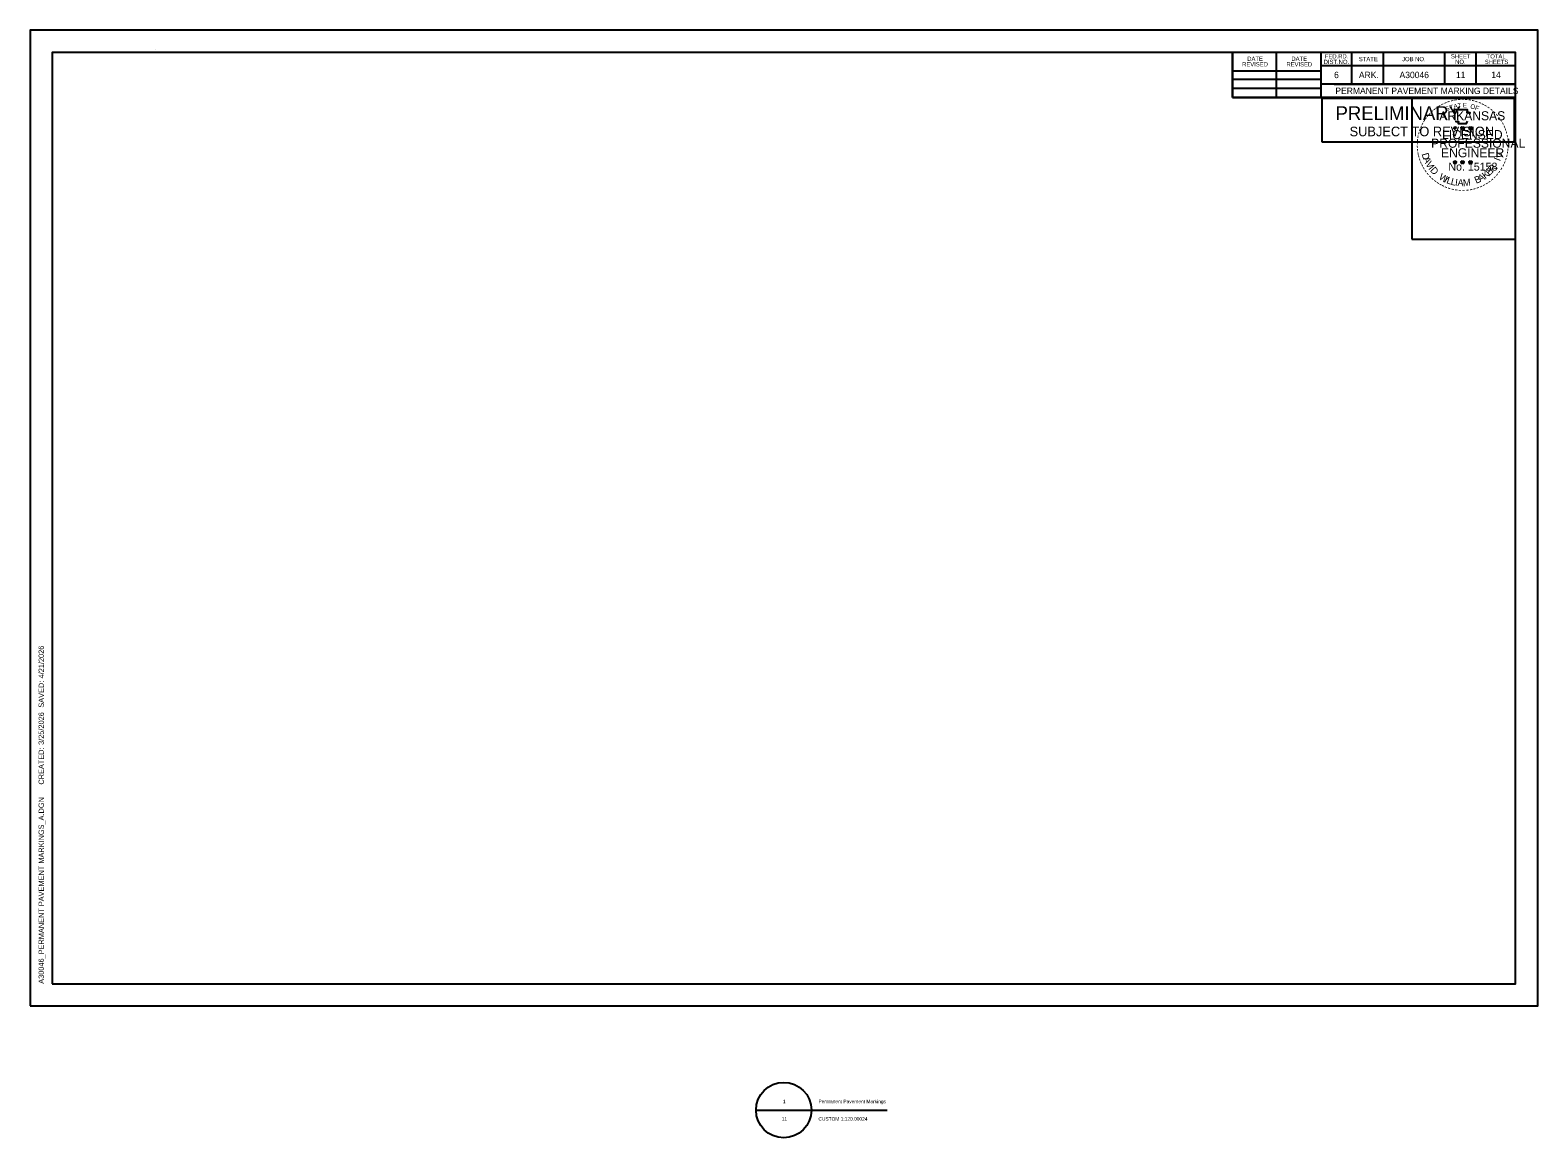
# Model space of a CAD drawing. Extents: x 0 to 1.42, y -0.12 to 0.92.
import ezdxf

# ---------------------------------------------------------------- set-up
doc = ezdxf.new("R2010")
doc.units = 0
for name, color, linetype in [('Default', 7, 'Continuous'), ('SHET_Annotations', 7, 'Continuous'), ('SHET_Border-Lines', 7, 'Continuous'), ('SHET_Border-Text', 7, 'Continuous'), ('SHET_Stamp-Prelim', 7, 'Continuous'), ('SHET_Stamp-Seal', 7, 'Continuous')]:
    doc.layers.add(name, color=color, linetype=linetype)

msp = doc.modelspace()

# ---------------------------------------------------------------- linework, layer by layer
at = {"layer": 'Default'}
for p, q in [((0.6821, -0.0979), (0.7341, -0.0979)), ((0.7083, -0.0979), (0.8052, -0.0979))]:
    msp.add_line(p, q, dxfattribs=at)
msp.add_circle((0.7081, -0.0979), 0.026, dxfattribs=at)
at = {"layer": 'SHET_Border-Lines'}
for p, q in [((0.1176, 0.8988), (0.1176, 0.8988)), ((0.1176, 0.8988), (0.1176, 0.8988)), ((1.1296, 0.8534), (1.1296, 0.8958)), ((1.1711, 0.8534), (1.1711, 0.8958)), ((1.2127, 0.8958), (1.2127, 0.8534)), ((1.2417, 0.8958), (1.2417, 0.866)), ((1.2712, 0.8958), (1.2712, 0.866)), ((1.3289, 0.8958), (1.3289, 0.866)), ((1.3584, 0.8958), (1.3584, 0.866)), ((1.1296, 0.8786), (1.2127, 0.8786)), ((1.3958, 0.8832), (1.2127, 0.8832)), ((1.3958, 0.8833), (1.3958, 0.8833)), ((1.1296, 0.8706), (1.2127, 0.8706)), ((1.3958, 0.866), (1.2127, 0.866)), ((1.2252, 0.866), (1.3958, 0.866)), ((1.1296, 0.8622), (1.2127, 0.8622)), ((1.3958, 0.8534), (1.1296, 0.8534))]:
    msp.add_line(p, q, dxfattribs=at)
for points in [[(0, 0), (1.4167, 0), (1.4167, 0.9167), (0, 0.9167)], [(0.0208, 0.0208), (1.3958, 0.0208), (1.3958, 0.8958), (0.0208, 0.8958)], [(1.1296, 0.8534), (1.3958, 0.8534), (1.3958, 0.8958), (1.1296, 0.8958)]]:
    msp.add_lwpolyline(points, close=True, dxfattribs=at)
at = {"layer": 'SHET_Stamp-Prelim'}
msp.add_lwpolyline([(1.2137, 0.8119), (1.3948, 0.8119), (1.3948, 0.8524), (1.2137, 0.8524)], close=True, dxfattribs=at)
at = {"layer": 'SHET_Stamp-Seal'}
for p, q in [((1.3373, 0.8252), (1.3388, 0.8247)), ((1.3373, 0.8252), (1.3384, 0.825)), ((1.3373, 0.8252), (1.3383, 0.8247)), ((1.3379, 0.8235), (1.3388, 0.8247)), ((1.3379, 0.8235), (1.3384, 0.8245)), ((1.3379, 0.8235), (1.3388, 0.8244)), ((1.3388, 0.8263), (1.3386, 0.8252)), ((1.3388, 0.8247), (1.3388, 0.8263)), ((1.3388, 0.8263), (1.339, 0.8252)), ((1.3403, 0.8252), (1.3388, 0.8247)), ((1.3397, 0.8235), (1.3388, 0.8247)), ((1.3397, 0.8235), (1.3388, 0.8244)), ((1.3403, 0.8252), (1.3391, 0.825)), ((1.3397, 0.8235), (1.3391, 0.8247)), ((1.3403, 0.8252), (1.3394, 0.8248)), ((1.3444, 0.8252), (1.3459, 0.8247)), ((1.3444, 0.8252), (1.3455, 0.825)), ((1.3444, 0.8252), (1.3454, 0.8247)), ((1.345, 0.8235), (1.3459, 0.8247)), ((1.345, 0.8235), (1.3455, 0.8245)), ((1.345, 0.8235), (1.3459, 0.8244)), ((1.3459, 0.8263), (1.3457, 0.8252)), ((1.3459, 0.8247), (1.3459, 0.8263)), ((1.3459, 0.8263), (1.3461, 0.8252)), ((1.3474, 0.8252), (1.3459, 0.8247)), ((1.3468, 0.8235), (1.3459, 0.8247)), ((1.3468, 0.8235), (1.3459, 0.8244)), ((1.3474, 0.8252), (1.3462, 0.825)), ((1.3468, 0.8235), (1.3462, 0.8247)), ((1.3474, 0.8252), (1.3465, 0.8248)), ((1.3519, 0.8252), (1.3534, 0.8247)), ((1.3519, 0.8252), (1.353, 0.825)), ((1.3519, 0.8252), (1.3529, 0.8246)), ((1.3525, 0.8234), (1.3534, 0.8247)), ((1.3525, 0.8234), (1.353, 0.8245)), ((1.3525, 0.8234), (1.3534, 0.8243)), ((1.3534, 0.8262), (1.3532, 0.8252)), ((1.3534, 0.8247), (1.3534, 0.8262)), ((1.3534, 0.8262), (1.3536, 0.8252)), ((1.3549, 0.8252), (1.3534, 0.8247)), ((1.3543, 0.8234), (1.3534, 0.8247)), ((1.3543, 0.8234), (1.3534, 0.8243)), ((1.3549, 0.8252), (1.3537, 0.825)), ((1.3543, 0.8234), (1.3537, 0.8247)), ((1.3549, 0.8252), (1.354, 0.8247)), ((1.3388, 0.7941), (1.3386, 0.793)), ((1.3388, 0.7926), (1.3388, 0.7941)), ((1.3388, 0.7941), (1.339, 0.793)), ((1.3459, 0.7941), (1.3457, 0.793)), ((1.3459, 0.7926), (1.3459, 0.7941)), ((1.3459, 0.7941), (1.3461, 0.793)), ((1.3534, 0.7941), (1.3532, 0.793)), ((1.3534, 0.7925), (1.3534, 0.7941)), ((1.3534, 0.7941), (1.3536, 0.793)), ((1.3373, 0.793), (1.3388, 0.7926)), ((1.3373, 0.793), (1.3384, 0.7928)), ((1.3373, 0.793), (1.3383, 0.7925)), ((1.3379, 0.7913), (1.3388, 0.7926)), ((1.3379, 0.7913), (1.3384, 0.7923)), ((1.3379, 0.7913), (1.3388, 0.7922)), ((1.3403, 0.793), (1.3388, 0.7926)), ((1.3397, 0.7913), (1.3388, 0.7926)), ((1.3397, 0.7913), (1.3388, 0.7922)), ((1.3403, 0.793), (1.3391, 0.7928)), ((1.3397, 0.7913), (1.3391, 0.7925)), ((1.3403, 0.793), (1.3394, 0.7926)), ((1.3444, 0.793), (1.3459, 0.7926)), ((1.3444, 0.793), (1.3455, 0.7928)), ((1.3444, 0.793), (1.3454, 0.7925)), ((1.345, 0.7913), (1.3459, 0.7926)), ((1.345, 0.7913), (1.3455, 0.7923)), ((1.345, 0.7913), (1.3459, 0.7922)), ((1.3474, 0.793), (1.3459, 0.7926)), ((1.3468, 0.7913), (1.3459, 0.7926)), ((1.3468, 0.7913), (1.3459, 0.7922)), ((1.3474, 0.793), (1.3461, 0.7928)), ((1.3468, 0.7913), (1.3462, 0.7925)), ((1.3474, 0.793), (1.3465, 0.7926)), ((1.3519, 0.793), (1.3534, 0.7925)), ((1.3519, 0.793), (1.353, 0.7928)), ((1.3519, 0.793), (1.3529, 0.7925)), ((1.3525, 0.7912), (1.3534, 0.7925)), ((1.3525, 0.7912), (1.353, 0.7923)), ((1.3525, 0.7912), (1.3534, 0.7922)), ((1.3549, 0.793), (1.3534, 0.7925)), ((1.3543, 0.7912), (1.3534, 0.7925)), ((1.3543, 0.7912), (1.3534, 0.7922)), ((1.3549, 0.793), (1.3537, 0.7928)), ((1.3543, 0.7912), (1.3537, 0.7925)), ((1.3549, 0.793), (1.354, 0.7926))]:
    msp.add_line(p, q, dxfattribs=at)
msp.add_lwpolyline([(1.2983, 0.7203), (1.3958, 0.7203), (1.3958, 0.8534), (1.2983, 0.8534)], close=True, dxfattribs=at)
for points in [[(1.3375, 0.8417), (1.3386, 0.8382)], [(1.3524, 0.8378), (1.353, 0.839), (1.3501, 0.8389), (1.3507, 0.8417), (1.3375, 0.8417)], [(1.3396, 0.8314), (1.3396, 0.831), (1.342, 0.8309), (1.3418, 0.8289), (1.3497, 0.8289), (1.3506, 0.8312)], [(1.3459, 0.8263), (1.3468, 0.8235), (1.3444, 0.8252), (1.3474, 0.8252), (1.345, 0.8235), (1.3459, 0.8263)], [(1.3534, 0.8262), (1.3543, 0.8234), (1.3519, 0.8252), (1.3549, 0.8252), (1.3525, 0.8234), (1.3534, 0.8262)], [(1.3388, 0.7941), (1.3397, 0.7913), (1.3373, 0.793), (1.3403, 0.793), (1.3379, 0.7913), (1.3388, 0.7941)], [(1.3459, 0.7941), (1.3468, 0.7913), (1.3444, 0.793), (1.3474, 0.793), (1.345, 0.7913), (1.3459, 0.7941)], [(1.3534, 0.7941), (1.3543, 0.7912), (1.3519, 0.793), (1.3549, 0.793), (1.3525, 0.7912), (1.3534, 0.7941)]]:
    msp.add_lwpolyline(points, dxfattribs=at)
for centre, radius in [((1.3388, 0.8247), 0.000732), ((1.3388, 0.8247), 0.000614), ((1.3388, 0.8247), 0.000492), ((1.3388, 0.8247), 0.000421), ((1.3388, 0.8247), 0.000318), ((1.3388, 0.8247), 0.000211), ((1.3388, 0.8247), 0.000126), ((1.3459, 0.8247), 0.000732), ((1.3459, 0.8247), 0.000614), ((1.3459, 0.8247), 0.000492), ((1.3459, 0.8247), 0.000421), ((1.3459, 0.8247), 0.000318), ((1.3459, 0.8247), 0.000211), ((1.3459, 0.8247), 0.000126), ((1.3534, 0.8247), 0.000732), ((1.3534, 0.8247), 0.000614), ((1.3534, 0.8247), 0.000492), ((1.3534, 0.8247), 0.000421), ((1.3534, 0.8247), 0.000318), ((1.3534, 0.8247), 0.000211), ((1.3534, 0.8247), 0.000126), ((1.3388, 0.7926), 0.000732), ((1.3388, 0.7926), 0.000614), ((1.3388, 0.7926), 0.000492), ((1.3388, 0.7926), 0.000421), ((1.3388, 0.7926), 0.000318), ((1.3388, 0.7926), 0.000211), ((1.3388, 0.7926), 0.000126), ((1.3459, 0.7926), 0.000732), ((1.3459, 0.7926), 0.000614), ((1.3459, 0.7926), 0.000492), ((1.3459, 0.7926), 0.000421), ((1.3459, 0.7926), 0.000318), ((1.3459, 0.7926), 0.000211), ((1.3459, 0.7926), 0.000126), ((1.3534, 0.7925), 0.000732), ((1.3534, 0.7925), 0.000614), ((1.3534, 0.7925), 0.000492), ((1.3534, 0.7925), 0.000421), ((1.3534, 0.7925), 0.000318), ((1.3534, 0.7925), 0.000211), ((1.3534, 0.7925), 0.000126)]:
    msp.add_circle(centre, radius, dxfattribs=at)

# ---------------------------------------------------------------- texts
at = {"layer": 'Default'}
for s, height, p in [('1', 0.00328, (0.7073, -0.0914)), ('Permanent Pavement Markings', 0.003281, (0.7407, -0.0914)), ('11', 0.00328, (0.7062, -0.1078)), ('CUSTOM 1:120.00024', 0.003281, (0.7407, -0.1078))]:
    msp.add_text(s, height=height, dxfattribs=at).set_placement(p)
at = {"layer": 'SHET_Annotations'}
for s, p in [('6', (1.2252, 0.8716)), ('ARK.', (1.2485, 0.8716)), ('A30046', (1.2867, 0.8716)), ('11', (1.3397, 0.8716)), ('14', (1.3729, 0.8717)), ('PERMANENT PAVEMENT MARKING DETAILS', (1.2264, 0.8567))]:
    msp.add_text(s, height=0.006, dxfattribs=at).set_placement(p)
at = {"layer": 'SHET_Border-Text'}
for s, p in [('FED.RD.', (1.2165, 0.8901)), ('SHEET', (1.335, 0.8901)), ('TOTAL', (1.3686, 0.8901)), ('REVISED', (1.1388, 0.8826)), ('DATE', (1.1436, 0.8878)), ('REVISED', (1.1804, 0.8826)), ('DATE', (1.1851, 0.8878)), ('DIST.NO.', (1.2154, 0.8849)), ('STATE', (1.2485, 0.8875)), ('JOB NO.', (1.2891, 0.8875)), ('NO.', (1.339, 0.8849)), ('SHEETS', (1.3668, 0.8849))]:
    msp.add_text(s, height=0.004, dxfattribs=at).set_placement(p)
for s, p in [('4/21/2026', (0.0129, 0.3077)), ('  SAVED: ', (0.0129, 0.2763)), ('3/25/2026', (0.0129, 0.2452)), ('     CREATED: ', (0.0129, 0.1983)), ('A30046_PERMANENT PAVEMENT MARKINGS_A.DGN', (0.0129, 0.0208))]:
    msp.add_text(s, height=0.005, rotation=90, dxfattribs=at).set_placement(p)
at = {"layer": 'SHET_Stamp-Prelim'}
for s, height, p in [('PRELIMINARY', 0.013, (1.2266, 0.8322)), ('SUBJECT TO REVISION', 0.009, (1.2398, 0.817))]:
    msp.add_text(s, height=height, dxfattribs=at).set_placement(p)
at = {"layer": 'SHET_Stamp-Seal'}
for s, height, rotation, p in [('-', 0.0068, 19.1761, (1.3322, 0.8465)), ('-', 0.0068, 13.6302, (1.3354, 0.8475)), ('-', 0.0068, 10.2193, (1.3383, 0.8482)), ('-', 0.0068, 5.8968, (1.3414, 0.8487)), ('-', 0.0068, 0.1862, (1.3446, 0.849)), ('-', 0.0068, 357.743, (1.3477, 0.8489)), ('-', 0.0068, 352.1617, (1.3509, 0.8487)), ('-', 0.0068, 347.2049, (1.3539, 0.8482)), ('-', 0.0068, 342.3362, (1.3566, 0.8475)), ('-', 0.0068, 50.6142, (1.3143, 0.8333)), ('-', 0.0068, 48.4231, (1.316, 0.8353)), ('-', 0.0068, 42.9622, (1.3179, 0.8374)), ('-', 0.0068, 38.9507, (1.3198, 0.8391)), ('-', 0.0068, 36.2317, (1.3218, 0.8407)), ('-', 0.0068, 34.0636, (1.3243, 0.8424)), ('-', 0.0068, 28.7918, (1.3268, 0.844)), ('-', 0.0068, 24.3072, (1.3295, 0.8453)), ('S', 0.00425, 21.594, (1.3305, 0.8403)), ('T', 0.00425, 16.4036, (1.3344, 0.8417)), ('A', 0.00425, 11.2132, (1.3379, 0.8428)), ('T', 0.00425, 6.0228, (1.3415, 0.8435)), ('E', 0.00425, 0.8323, (1.3462, 0.844)), ('O', 0.00425, 350.4515, (1.353, 0.8431)), ('F', 0.00425, 340.0707, (1.3571, 0.8421)), ('-', 0.0068, 337.8551, (1.3597, 0.8466)), ('-', 0.0068, 334.1211, (1.3624, 0.8454)), ('-', 0.0068, 329.6409, (1.3649, 0.8442)), ('-', 0.0068, 325.8627, (1.3676, 0.8427)), ('-', 0.0068, 320.5297, (1.3702, 0.8409)), ('-', 0.0068, 315.5786, (1.3728, 0.8388)), ('-', 0.0068, 309.8797, (1.3752, 0.8365)), ('-', 0.0068, 72.3945, (1.3078, 0.8207)), ('-', 0.0068, 67.7743, (1.3088, 0.8234)), ('-', 0.0068, 62.8713, (1.3099, 0.826)), ('-', 0.0068, 58.0706, (1.3112, 0.8286)), ('-', 0.0068, 54.2325, (1.3126, 0.8309)), ('-', 0.0068, 306.6522, (1.3774, 0.8339)), ('-', 0.00595, 303.6753, (1.3795, 0.8315)), ('-', 0.0068, 299.6684, (1.3808, 0.8289)), ('-', 0.0068, 294.6628, (1.3822, 0.8263)), ('-', 0.0068, 290.5728, (1.3833, 0.8239)), ('-', 0.0068, 285.1233, (1.3843, 0.8214)), ('-', 0.0068, 89.0622, (1.306, 0.8088)), ('-', 0.0068, 94.1959, (1.3061, 0.8057)), ('-', 0.0068, 85.1863, (1.3061, 0.8117)), ('-', 0.0068, 81.2013, (1.3064, 0.8147)), ('-', 0.0068, 75.461, (1.307, 0.8177)), ('-', 0.0068, 280.5493, (1.3851, 0.8182)), ('-', 0.0068, 276.5962, (1.3858, 0.815)), ('-', 0.0068, 274.3301, (1.3861, 0.8119)), ('-', 0.0068, 269.9407, (1.3862, 0.8092)), ('-', 0.0068, 98.9479, (1.3065, 0.8028)), ('-', 0.0068, 101.7149, (1.307, 0.7997)), ('-', 0.0068, 105.4578, (1.3077, 0.7972)), ('-', 0.0068, 109.0874, (1.3086, 0.7945)), ('-', 0.0068, 114.0643, (1.3097, 0.792)), ('D', 0.00654, 286.2848, (1.3074, 0.8003)), ('A', 0.00654, 292.7835, (1.3086, 0.796)), ('V', 0.00654, 300.7936, (1.3108, 0.791)), ('I', 0.00654, 69.0301, (1.3812, 0.7931)), ('V', 0.00654, 72.6573, (1.3822, 0.7954)), ('-', 0.0068, 247.8887, (1.3837, 0.7948)), ('-', 0.0068, 252.8681, (1.3846, 0.7977)), ('-', 0.0068, 255.7626, (1.3854, 0.8007)), ('-', 0.0068, 260.9953, (1.3858, 0.8036)), ('-', 0.0068, 263.5172, (1.3861, 0.8064)), ('-', 0.0068, 115.7289, (1.311, 0.7894)), ('-', 0.0068, 120.4471, (1.3125, 0.7869)), ('-', 0.0068, 125.8934, (1.3142, 0.7845)), ('-', 0.0068, 130.7181, (1.3162, 0.7821)), ('I', 0.00654, 308.3502, (1.3135, 0.7866)), ('-', 0.0068, 134.2238, (1.3184, 0.7798)), ('D', 0.00654, 311.9774, (1.315, 0.7847)), ('W', 0.00654, 328.0731, (1.323, 0.7771)), ('I', 0.00654, 336.6877, (1.328, 0.7741)), ('B', 0.00654, 22.8589, (1.3587, 0.7723)), ('A', 0.00654, 28.9042, (1.3625, 0.7739)), ('K', 0.00654, 36.9143, (1.3672, 0.7766)), ('E', 0.00654, 44.0175, (1.3711, 0.7795)), ('R', 0.00654, 50.3651, (1.3742, 0.7825)), ('-', 0.0068, 225.7653, (1.3753, 0.7814)), (',', 0.00654, 57.4684, (1.3773, 0.7863)), ('-', 0.0068, 231.2538, (1.3773, 0.7838)), ('-', 0.0068, 233.8452, (1.3792, 0.7862)), ('-', 0.0068, 239.0712, (1.3809, 0.789)), ('-', 0.0068, 244.6197, (1.3825, 0.7921)), ('-', 0.0068, 138.9338, (1.3206, 0.7778)), ('-', 0.0068, 144.6463, (1.323, 0.7761)), ('-', 0.0068, 148.0898, (1.3254, 0.7745)), ('-', 0.0068, 151.5704, (1.3278, 0.7732)), ('-', 0.0068, 154.6002, (1.3301, 0.7721)), ('-', 0.0068, 158.5612, (1.3327, 0.771)), ('L', 0.00654, 340.3149, (1.3303, 0.7731)), ('-', 0.0068, 162.7983, (1.3356, 0.7701)), ('L', 0.00654, 346.6625, (1.3344, 0.7716)), ('-', 0.0068, 167.5555, (1.3387, 0.7694)), ('-', 0.0068, 173.1155, (1.3419, 0.769)), ('I', 0.00654, 353.0101, (1.3386, 0.7706)), ('A', 0.00654, 356.6373, (1.341, 0.7703)), ('-', 0.0068, 176.5183, (1.3451, 0.7687)), ('-', 0.0068, 181.5918, (1.3483, 0.7688)), ('M', 0.00654, 4.6473, (1.3465, 0.77)), ('-', 0.0068, 185.8167, (1.3517, 0.7691)), ('-', 0.0068, 191.2858, (1.3549, 0.7697)), ('-', 0.0068, 195.4743, (1.358, 0.7705)), ('-', 0.0068, 199.4643, (1.3608, 0.7716)), ('-', 0.0068, 204.2516, (1.3635, 0.7727)), ('-', 0.0068, 207.3568, (1.3661, 0.7741)), ('-', 0.0068, 212.2491, (1.3685, 0.7756)), ('-', 0.0068, 215.7363, (1.3708, 0.7772)), ('-', 0.0068, 221.0851, (1.3731, 0.7792))]:
    msp.add_text(s, height=height, rotation=rotation, dxfattribs=at).set_placement(p)
for s, height, p in [('ARKANSAS', 0.0085, (1.3241, 0.832)), ('LICENSED', 0.0085, (1.3267, 0.8143)), ('PROFESSIONAL', 0.0085, (1.3164, 0.8062)), ('ENGINEER', 0.0085, (1.3257, 0.7972)), ('No. 15158', 0.00747, (1.3326, 0.7847)), ('AAMU', 0.000000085, (1.3456, 0.77))]:
    msp.add_text(s, height=height, dxfattribs=at).set_placement(p)

doc.saveas('drawing.dxf')
